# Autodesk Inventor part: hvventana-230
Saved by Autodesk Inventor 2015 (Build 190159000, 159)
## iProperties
Created: 2020-08
Part Number: hvventana-230
Checked By: TraceParts S.A.
Material: Generic
Catalog Web Link: www.traceparts.com
Document SubType Name: Modeling
Designer: TraceParts
Density: 1 g/cm^3
Appearance: Default
Company: TraceParts S.A.
Author: TraceParts
REFERENCE: HVVENTANA-230
DESIGN: HVVENTANA-230
SUPPLIER: Soler & Palau
TraceParts.PartNumber: 10-04022019-080750
TraceParts.PartTitle: HV-STYLVENT
TraceParts.InstanceId: 10-04022019-0807503O47J730AQ22IUF1EVLWX46AV
TraceParts.PartStatus: Published
TraceParts.PartVersion: 1.0.1
TRACEPARTS: TRACEPARTS
TraceParts.PartLanguage: en
TraceParts.ClassPath: SOLER_PALAU:10-04022019-080750
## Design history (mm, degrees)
feature "hvventana-230"
body "Solid1"
